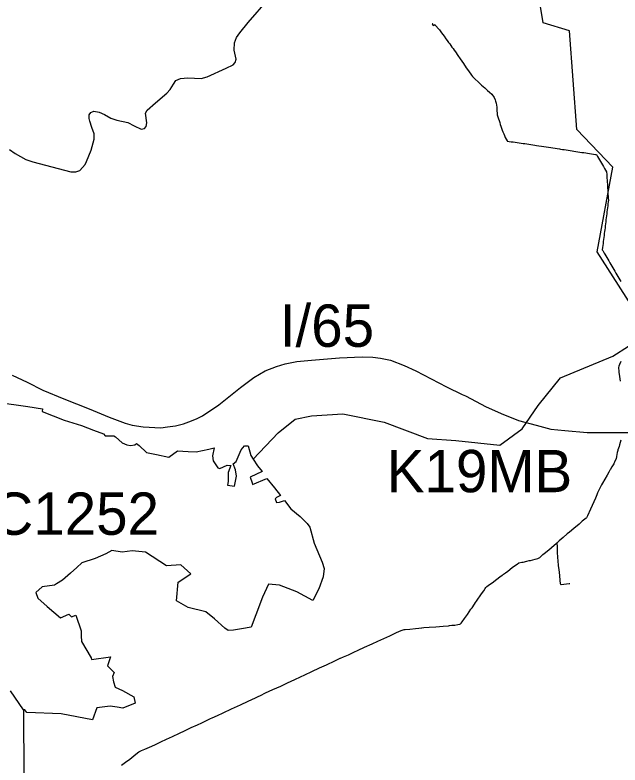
# Model space of a CAD drawing. Extents: x -789162 to -606354, y -1062736 to -945481.
# Drawn here: x -685366 to -683220, y -984501 to -981843 of the extents above; entities that cross this region are included whole.
import ezdxf

# ---------------------------------------------------------------- set-up
doc = ezdxf.new("R2010")
doc.units = 0
for name, color, linetype in [('_SIRSI VZTAHY_CYKLOTRASY MISTNI S', 7, 'Continuous'), ('_SIRSI VZTAHY_SILNICE I a II TRIDY_STAV POPIS', 7, 'Continuous'), ('_SIRSI VZTAHY_SILNICE I TRIDY_STAV', 7, 'Continuous'), ('_SIRSI VZTAHY_SILNICE III TRIDY_STAV', 7, 'Continuous'), ('_SIRSI VZTAHY_USES_NRBK_S', 7, 'Continuous'), ('_SIRSI VZTAHY_USES_popis S', 7, 'Continuous'), ('_SIRSI VZTAHY_USES_RBC_S', 7, 'Continuous'), ('_SIRSI VZTAHY_USES_RBK_S', 7, 'Continuous'), ('_SIRSI VZTAHY_VTL PLYNOVOD', 7, 'Continuous')]:
    doc.layers.add(name, color=color, linetype=linetype)

msp = doc.modelspace()

# ---------------------------------------------------------------- linework, layer by layer
at = {"layer": '_SIRSI VZTAHY_CYKLOTRASY MISTNI S'}
msp.add_lwpolyline([(-682749.1, -983758.6), (-682819.7, -983691.1), (-682854.2, -983537), (-682952.4, -983284.6), (-683097.1, -982950.5), (-683142.3, -982931.9), (-683301.6, -982682.1), (-683245.8, -982381.9), (-683373.3, -982249), (-683399.8, -981898.3), (-683492.8, -981870.4), (-683539.2, -981586.7), (-683511.3, -981493.7), (-683469.5, -981326.4)], dxfattribs=at)
at = {"layer": '_SIRSI VZTAHY_SILNICE I TRIDY_STAV'}
msp.add_lwpolyline([(-685375.4, -983119.6), (-685322.2, -983143.6), (-685266.7, -983171.8), (-685193.3, -983203), (-685103.4, -983239.1), (-685031.5, -983267.7), (-684975.5, -983288.9), (-684950.2, -983296.1), (-684911.8, -983302.1), (-684849.2, -983305.4), (-684825.2, -983302.2), (-684797.1, -983298.6), (-684768.8, -983291.4), (-684740.2, -983281.3), (-684719.9, -983273), (-684701.2, -983263.5), (-684643.2, -983224.8), (-684566.5, -983162.5), (-684519.4, -983127.2), (-684478.5, -983104.3), (-684438.9, -983089), (-684407.7, -983078.6), (-684366.1, -983071), (-684314, -983066.1), (-684215.2, -983058), (-684134.4, -983054), (-684097.5, -983056), (-684069.4, -983058.9), (-684034, -983066.6), (-683985.8, -983084.4), (-683944.1, -983103.8), (-683835.8, -983160.4), (-683779.7, -983187.4), (-683768.2, -983192.9), (-683748.7, -983203.6), (-683697.6, -983229.9), (-683642.2, -983255.2), (-683580.9, -983279.7), (-683517.4, -983296.9), (-683466, -983310.2), (-683415.6, -983315.6), (-683337.2, -983322.9), (-683184.5, -983322.7)], dxfattribs=at)
at = {"layer": '_SIRSI VZTAHY_SILNICE III TRIDY_STAV'}
msp.add_lwpolyline([(-685384.9, -982319.2), (-685365, -982332.9), (-685327.9, -982354.3), (-685302.3, -982362.9), (-685167.8, -982399), (-685150.2, -982399), (-685135.5, -982393.8), (-685117.1, -982372.4), (-685112.1, -982361.9), (-685095.6, -982321.5), (-685084.6, -982283.1), (-685085.6, -982263.6), (-685093.2, -982241.7), (-685100.8, -982218.9), (-685103.2, -982208.9), (-685102.4, -982196.8), (-685097.5, -982188), (-685086.1, -982183.7), (-685067.5, -982187.1), (-685048.5, -982195.6), (-685025.6, -982207.8), (-685004.4, -982215.8), (-684966, -982224.1), (-684943.9, -982235.2), (-684918.3, -982247.4), (-684906.2, -982245.3), (-684900.3, -982237.4), (-684898.7, -982224.7), (-684903.1, -982190.7), (-684897.1, -982179.9), (-684867.2, -982154.2), (-684827.9, -982119.9), (-684815.8, -982106.9), (-684804.4, -982087.5), (-684795.3, -982074.9), (-684779.1, -982067.3), (-684753.3, -982065), (-684705.6, -982068.1), (-684684.1, -982062.1), (-684617.2, -982030.9), (-684592.6, -982018.9), (-684584.7, -982011.3), (-684582.1, -981999.6), (-684589.1, -981966.9), (-684587.8, -981941.1), (-684580.9, -981922.1), (-684568.4, -981906.2), (-684538.6, -981869.1), (-684466.8, -981785.4)], dxfattribs=at)
at = {"layer": '_SIRSI VZTAHY_USES_NRBK_S'}
msp.add_lwpolyline([(-684521.5, -983417.3), (-684432.8, -983323.6), (-684372.1, -983275), (-684314.4, -983262.8), (-684203.7, -983256.8), (-684056.5, -983285.6), (-683903.3, -983343.3), (-683803.1, -983350.9), (-683646.8, -983367.6), (-683567.9, -983309.9), (-683510.3, -983226.4), (-683431.4, -983129.2), (-683246.3, -983051.8), (-683190.1, -983016.9)], dxfattribs=at)
at = {"layer": '_SIRSI VZTAHY_USES_RBC_S'}
msp.add_lwpolyline([(-685413.3, -983217.3), (-685361.9, -983224.5), (-685320.8, -983230.1), (-685268.8, -983239.1), (-685269.8, -983247.6), (-685191, -983279.2), (-685130.3, -983298.2), (-685087.3, -983313.7), (-685051.7, -983326.6), (-685046.6, -983334.6), (-685019.7, -983333.9), (-685015.4, -983334.8), (-685009.3, -983337.6), (-684997.3, -983348.2), (-684985.3, -983358.7), (-684969.3, -983365.6), (-684955.9, -983368.5), (-684940.8, -983365.8), (-684934.8, -983361.2), (-684925.3, -983368.3), (-684899.2, -983393.1), (-684864.4, -983400.2), (-684820.1, -983409.3), (-684790, -983387.7), (-684751.3, -983389.5), (-684723.2, -983390.5), (-684678.9, -983381), (-684659.9, -983376.9), (-684665.1, -983404.7), (-684663.6, -983423.4), (-684647.2, -983447.5), (-684639.1, -983450.5), (-684614, -983437.7), (-684600, -983438.9), (-684609.4, -983464), (-684610.2, -983496.1), (-684612.3, -983509.4), (-684587.9, -983512.9), (-684580.9, -983477.3), (-684583.4, -983454.6), (-684591.7, -983434), (-684581.1, -983425.4), (-684564, -983384.4), (-684552.4, -983370.2), (-684538.7, -983370), (-684530, -983403.4), (-684521.5, -983417.3), (-684506.2, -983441.1), (-684489.3, -983460.5), (-684532.5, -983480.8), (-684524.6, -983501.1), (-684523.2, -983506.2), (-684472.7, -983485.4), (-684445.1, -983518.2), (-684424, -983545.6), (-684438.4, -983553.4), (-684443.5, -983557.8), (-684439, -983570.1), (-684427.4, -983569), (-684409.8, -983563), (-684388.1, -983593.2), (-684354.6, -983620), (-684329.7, -983645), (-684320.9, -983658.3), (-684305.5, -983714.5), (-684276.7, -983782), (-684269, -983804.5), (-684273.6, -983834.6), (-684288.4, -983877.1), (-684310, -983918), (-684366.5, -983886.9), (-684427.6, -983863.1), (-684466.9, -983860.4), (-684488.3, -983906.7), (-684512.4, -983968.5), (-684528.5, -984012.9), (-684563.1, -984018.5), (-684591.6, -984023.1), (-684610.2, -984024.2), (-684621.5, -984015.6), (-684658.4, -983983.2), (-684688.9, -983957.9), (-684751.8, -983942.2), (-684793.5, -983919.6), (-684787.3, -983853.5), (-684741.8, -983823.3), (-684777.7, -983792.1), (-684828.4, -983795.2), (-684903.5, -983747.1), (-684950.6, -983742.3), (-684986.4, -983747.2), (-685022.3, -983740.2), (-685043.4, -983752.7), (-685081.9, -983768.6), (-685128.6, -983784.5), (-685146.6, -983801.5), (-685168.6, -983821.1), (-685197.6, -983846), (-685218.3, -983858.6), (-685225.7, -983864.1), (-685269.3, -983869.6), (-685292.3, -983889.7), (-685285, -983909.1), (-685252.2, -983939), (-685204.6, -983979.2), (-685174.8, -983966.8), (-685166, -983975.8), (-685149.9, -983969.8), (-685131, -984024.9), (-685131, -984042.9), (-685129.7, -984063.5), (-685095.4, -984121.3), (-685094.4, -984127.5), (-685027.6, -984117.5), (-685037.5, -984149.4), (-685014.1, -984172.8), (-685020.6, -984187.1), (-685016.7, -984206.5), (-685011.2, -984225), (-684985.1, -984237), (-684944.5, -984259.2), (-684939.6, -984282.2), (-684983.2, -984299.9), (-685003.1, -984295.6), (-685028, -984292.9), (-685075.2, -984298.9), (-685090.9, -984341.1), (-685202.5, -984319.4), (-685324.5, -984314.9), (-685331.5, -984305.5), (-685336.2, -984304.9), (-685381.9, -984238.4)], dxfattribs=at)
at = {"layer": '_SIRSI VZTAHY_USES_RBK_S'}
msp.add_lwpolyline([(-685336.2, -984304.9), (-685335.2, -984542.8), (-685252.9, -984657.1), (-685006, -984774), (-684907.7, -984787.3), (-684705.9, -984909.5), (-684528, -985068.9), (-684419.2, -985363.9), (-684408.6, -985531.3), (-684464.3, -985717.2), (-684586.5, -985911.2), (-684681.7, -985979.5), (-684736, -986021.3)], dxfattribs=at)
at = {"layer": '_SIRSI VZTAHY_VTL PLYNOVOD'}
for points in [[(-683884.7, -981873.9), (-683884.8, -981874), (-683885.3, -981874.3), (-683885.4, -981874.4), (-683885.6, -981874.5), (-683886.1, -981874.9), (-683886.2, -981875), (-683886.2, -981875), (-683886.5, -981875.2), (-683886.6, -981875.3), (-683883.4, -981879.8), (-683877.6, -981876), (-683876.6, -981877.2), (-683860.6, -981894.9), (-683853, -981905.4), (-683844.4, -981917.3), (-683837.9, -981926.5), (-683833.1, -981933.1), (-683828.3, -981939.6), (-683824.4, -981945.1), (-683820.6, -981950.6), (-683816.5, -981956.2), (-683812.5, -981961.8), (-683808.4, -981967.7), (-683804.2, -981973.5), (-683795.5, -981986.4), (-683787.5, -981998.2), (-683775.7, -982014.8), (-683765.5, -982029.5), (-683758, -982040.6), (-683747.6, -982056), (-683743.1, -982060.8), (-683734.7, -982069), (-683722.6, -982080.5), (-683711.5, -982090.8), (-683699.8, -982101.3), (-683689.8, -982110.1), (-683683.2, -982115.8), (-683674.7, -982123.5), (-683666.1, -982134.7), (-683663.1, -982143.8), (-683661.7, -982148.2), (-683659.8, -982154.9), (-683658.3, -982161.9), (-683657.3, -982168.8), (-683657.1, -982175.8), (-683656.7, -982182.9), (-683656.4, -982189.9), (-683655.7, -982197), (-683653.6, -982203.6), (-683651.4, -982210.3), (-683649.2, -982217), (-683647, -982223.7), (-683644.8, -982230.4), (-683642.5, -982237.1), (-683640.1, -982243.7), (-683637.8, -982250.4), (-683635.4, -982257), (-683632.9, -982263.6), (-683630.1, -982270.1), (-683627.1, -982276.4), (-683623.9, -982282.7), (-683620.5, -982288.9), (-683620, -982290.1), (-683613.1, -982290.8), (-683606.1, -982291.8), (-683599.1, -982292.6), (-683592.1, -982293.6), (-683585.2, -982294.6), (-683578.2, -982295.6), (-683571.3, -982296.6), (-683564.4, -982297.5), (-683557.5, -982298.6), (-683550.6, -982299.7), (-683543.8, -982300.7), (-683536.9, -982301.6), (-683529.9, -982302.5), (-683522.9, -982303.6), (-683516, -982304.6), (-683490.8, -982308.4), (-683482.4, -982309.8), (-683474, -982311.1), (-683434.5, -982317.3), (-683432, -982317.7), (-683424.7, -982318.8), (-683418.1, -982319.8), (-683411.3, -982320.8), (-683404.5, -982321.9), (-683397.5, -982323), (-683390.6, -982324.1), (-683383.6, -982325.2), (-683376.7, -982326.3), (-683369.7, -982327.2), (-683362.8, -982328.3), (-683355.9, -982329.4), (-683348.9, -982330.5), (-683342, -982331.6), (-683335.1, -982332.6), (-683328.1, -982333.6), (-683321.2, -982334.6), (-683314.3, -982335.6), (-683307.3, -982336.8), (-683304.1, -982337.4), (-683300.6, -982343.6), (-683297.1, -982349.7), (-683293.4, -982355.7), (-683289.9, -982361.8), (-683286.3, -982367.9), (-683282.8, -982374), (-683279.3, -982380), (-683275.7, -982386.1), (-683272.1, -982392.1), (-683268.6, -982398.3), (-683267.8, -982399.7), (-683267.5, -982406.7), (-683267.2, -982413.8), (-683266.6, -982420.9), (-683266.1, -982427.9), (-683265.6, -982435), (-683265.2, -982442), (-683264.7, -982449.1), (-683264.3, -982456.1), (-683263.9, -982463.2), (-683263.6, -982470.2), (-683263.2, -982477.3), (-683262.8, -982484.4), (-683262.3, -982491.4), (-683261.6, -982498.4), (-683262.4, -982505.4), (-683263.3, -982512.4), (-683264.1, -982519.4), (-683264.9, -982526.4), (-683265.8, -982533.4), (-683266.7, -982540.4), (-683267.6, -982547.4), (-683268.5, -982554.4), (-683269.4, -982561.4), (-683270.3, -982568.4), (-683271.1, -982575.5), (-683271.9, -982582.5), (-683272.7, -982589.4), (-683273.6, -982596.4), (-683274.5, -982603.5), (-683275.3, -982610.2), (-683276.2, -982617.2), (-683277.1, -982624.2), (-683278.1, -982631.2), (-683279, -982638.2), (-683279.9, -982645.2), (-683280.7, -982652.2), (-683281.6, -982659.3), (-683282.4, -982666.1), (-683283.1, -982674.8), (-683281.7, -982677.4), (-683281.5, -982677.8), (-683276.3, -982686.9), (-683276.1, -982687.2), (-683274.4, -982690), (-683271, -982696), (-683267.4, -982702.4), (-683263.8, -982708.5), (-683260.3, -982714.5), (-683256.8, -982720.6), (-683253.2, -982726.7), (-683249.6, -982732.8), (-683246.1, -982738.9), (-683242.6, -982745.1), (-683239, -982751.1), (-683235.5, -982757.2), (-683232, -982763.3), (-683228.5, -982769.5), (-683225.1, -982775.6), (-683221.5, -982781.7), (-683217.9, -982787.7)], [(-683217.9, -983070.4), (-683221.8, -983080.9), (-683221.8, -983080.9), (-683221.8, -983081), (-683224.1, -983087.5), (-683225.3, -983091.7), (-683225.5, -983095.2), (-683224.8, -983102.3), (-683224.3, -983108.7), (-683222.5, -983123.5), (-683220.1, -983140.8)], [(-683217.1, -983349.7), (-683222.5, -983366.3), (-683223.8, -983371.6), (-683228.2, -983383.6), (-683228.4, -983386.2), (-683230, -983392.9), (-683232.8, -983408), (-683234.1, -983415.4), (-683238.5, -983423.9), (-683242.8, -983433), (-683248.9, -983443.7), (-683255.3, -983454.9), (-683256, -983456), (-683256, -983456.1), (-683259.9, -983462.7), (-683266.3, -983474.1), (-683282, -983501.6), (-683286.6, -983508.1), (-683297.6, -983531.4), (-683299.8, -983536.4), (-683302.5, -983543.3), (-683307.3, -983554.9), (-683313.1, -983568.1), (-683324.5, -983594.1), (-683335.5, -983617.5), (-683339.3, -983624.8), (-683340.1, -983625.9), (-683354, -983637.3), (-683365.6, -983646.9), (-683384.6, -983663.2), (-683400.1, -983676), (-683407.2, -983682.2), (-683421.9, -983694.9), (-683436.2, -983706.9), (-683443.4, -983713.3), (-683444.8, -983714.4), (-683445.5, -983714.9)], [(-684988.7, -984501.2), (-684974.1, -984490.9), (-684973.9, -984490.7), (-684973.9, -984490.7), (-684959.1, -984479.9), (-684945, -984468.8), (-684931.1, -984458.4), (-684926.2, -984454.5), (-684922.4, -984452.2), (-684922.3, -984452.1), (-684917, -984450), (-684905.7, -984445.1), (-684888.8, -984438), (-684869.6, -984429), (-684849.3, -984419.5), (-684828.2, -984409.9), (-684807, -984399.9), (-684782.2, -984387.9), (-684765, -984379.9), (-684740.8, -984368.4), (-684719.1, -984358.6), (-684703.1, -984351.5), (-684688.6, -984344.5), (-684679.2, -984339.5), (-684672.8, -984336.2), (-684666.7, -984334.1), (-684648.3, -984325.5), (-684628.1, -984316), (-684598.1, -984301.7), (-684566.6, -984287.2), (-684539.1, -984274.3), (-684513.5, -984262.5), (-684503.8, -984257.8), (-684503.6, -984257.7), (-684495.3, -984254.1), (-684477.6, -984245.8), (-684451.4, -984233.6), (-684423.6, -984221.1), (-684399.6, -984210), (-684374, -984198.2), (-684353.5, -984188.3), (-684353.5, -984188.3), (-684353.1, -984188.2), (-684338.3, -984181.6), (-684313.1, -984170), (-684285.6, -984156.9), (-684261.7, -984146.1), (-684231.8, -984132.1), (-684212.3, -984122.9), (-684212.3, -984122.9), (-684212.1, -984122.8), (-684200.4, -984117.8), (-684183.3, -984110.1), (-684164.2, -984101.3), (-684148.5, -984093.8), (-684126.4, -984083.7), (-684099.6, -984071.2), (-684079.6, -984062.3), (-684058.3, -984052.8), (-684036.4, -984042.8), (-684015.3, -984033), (-684002.4, -984026.9), (-683993.4, -984023.2), (-683985.6, -984021.1), (-683983.9, -984020.6), (-683981.7, -984020.6), (-683965.9, -984019.1), (-683946, -984016.9), (-683933.5, -984015.9), (-683924.2, -984015.4), (-683924.1, -984015.3), (-683923.6, -984015.3), (-683923.6, -984015.3), (-683915.7, -984014.1), (-683897.5, -984012.7), (-683873.8, -984011.1), (-683847.1, -984008.9), (-683829.1, -984007.4), (-683825.1, -984006.9), (-683825, -984006.9), (-683824.7, -984006.9), (-683816.9, -984005.7), (-683806.2, -984004.8), (-683795.1, -984003.4), (-683789, -984002.2), (-683786.5, -984000.6), (-683786.5, -984000.6), (-683786.3, -984000.5), (-683784, -983998.6), (-683780.5, -983994), (-683772.1, -983982.2), (-683761.2, -983967.6), (-683748.9, -983949.2), (-683745.1, -983943.9), (-683735.9, -983930.8), (-683732.4, -983925.6), (-683732.3, -983925.4), (-683728.9, -983920.7), (-683711.5, -983894.4), (-683703.6, -983883.6), (-683698.5, -983875.9), (-683696.1, -983871.8), (-683696.1, -983871.8), (-683696.1, -983871.6), (-683695.2, -983870.2), (-683694.4, -983869.2), (-683692.6, -983868.1), (-683683.3, -983861.7), (-683673.3, -983854.8), (-683657.4, -983842.8), (-683646.2, -983834.6), (-683638.4, -983828.6), (-683635.9, -983826.7), (-683635.9, -983826.7), (-683633.7, -983825), (-683626.7, -983819.9), (-683618.7, -983813.6), (-683602.3, -983801.5), (-683590.8, -983792.7), (-683590.7, -983792.7), (-683590.7, -983792.6), (-683585, -983788.6), (-683585, -983788.6), (-683578.6, -983784.9), (-683569.1, -983782.5), (-683563.5, -983781.6), (-683551.2, -983778.6), (-683542.4, -983776.4), (-683542.4, -983776.3), (-683541.7, -983776.2), (-683537.3, -983775.6), (-683521.4, -983771.6), (-683512, -983769.2), (-683505.1, -983765.3), (-683500.8, -983761.9), (-683493.7, -983755.3), (-683488.8, -983751.1), (-683473.1, -983738.4), (-683463.7, -983730.2), (-683454.1, -983722), (-683446.6, -983715.8), (-683445.8, -983715.2), (-683445.5, -983714.9)], [(-683445.5, -983714.9), (-683445.2, -983715.3), (-683444.9, -983715.6), (-683444.9, -983715.7), (-683444.8, -983716), (-683444.7, -983716.2), (-683444.6, -983716.5), (-683444, -983718.4), (-683443.4, -983723.3), (-683443.6, -983735.5), (-683443.3, -983746.2), (-683442.4, -983766.1), (-683441.3, -983777.4), (-683439.8, -983793.9), (-683439.8, -983795.1), (-683437.9, -983808.2), (-683435.4, -983829.6), (-683433.5, -983847.3), (-683432.2, -983857.9), (-683432, -983860.4), (-683430.7, -983860.9), (-683429.4, -983860.9), (-683419.1, -983859.6), (-683410.4, -983858.8), (-683400.8, -983858.1), (-683398.5, -983857.7), (-683398.5, -983857.7)]]:
    msp.add_lwpolyline(points, dxfattribs=at)

# ---------------------------------------------------------------- texts
at = {"layer": '_SIRSI VZTAHY_SILNICE I a II TRIDY_STAV POPIS'}
msp.add_text('I/65', height=150, dxfattribs=at).set_placement((-684426.9, -983018.7))
at = {"layer": '_SIRSI VZTAHY_USES_popis S'}
for s, p in [('K19MB', (-684047.6, -983534.2)), ('RC1252', (-685591.1, -983685.1))]:
    msp.add_text(s, height=150, dxfattribs=at).set_placement(p)

doc.saveas('drawing.dxf')
